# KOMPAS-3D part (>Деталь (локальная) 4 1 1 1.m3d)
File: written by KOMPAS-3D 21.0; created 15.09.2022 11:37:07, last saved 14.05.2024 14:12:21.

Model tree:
1. Эскиз:1

Referenced files in C:\Program Files\Ascon\Libs\EasySteel\: Rolled metal.kle, StandartSolutions.kle, DSTVProperties.lpt
Referenced files in W:\Шаблоны чертежей\: Констр. чертеж А3 гориз. перв. лист.cdt
Referenced files in C:\Program Files\Ascon\Libs\EasySteel\BeltEndings\: 
Referenced files in C:\Program Files\Ascon\Libs\EasySteel\Punctures\: 
Referenced files in C:\Program Files\Ascon\Libs\EasySteel\Insulations\: 
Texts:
  Уголок равнополочный по ГОСТ 8509-93 (Спец)
  config2DpacketName
  config2DstdSizeID
  Констр. чертеж А3 гориз. перв. лист.cdt
  Болт ГОСТ 22353-77
  Шайба ГОСТ 22355-77
  Гайка ГОСТ 22354-77
  Нормальная пружинная шайба ГОСТ 6402-70 (исп. 1)
  SeaRox SL 436
  Сталь 09Г2С ГОСТ 19281-2014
